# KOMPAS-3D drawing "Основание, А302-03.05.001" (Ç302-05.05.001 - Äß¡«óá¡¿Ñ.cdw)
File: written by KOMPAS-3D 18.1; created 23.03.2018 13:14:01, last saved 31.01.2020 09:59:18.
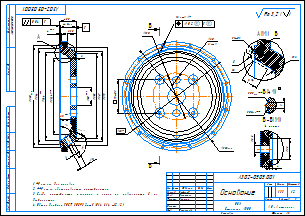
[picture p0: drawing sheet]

Sheet 1: A3, landscape

Document properties: Автор: Милов; Параметр неуказанной шероховатости: Ra 3,2; Полное имя файла: ..\3Д\А302-00.05.001 - Основание.m3d; Масса: 1.33492; Организация: Милов

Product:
- Part/product: Основание  | designation А302-03.05.001
    Материал: Полипропилен  ГОСТ 26996-86 (density 900 kg/m3)
    Масса: 1.33086
    Раздел спецификации: Детали
    Форматы листов документа: A3
- Part/product: Основание  | designation А302-00.05.001
    Материал: Полипропилен  ГОСТ 26996-86 (density 900 kg/m3)
    Масса: 1.33086
    Раздел спецификации: Детали
    Форматы листов документа: A3
    source file: \\192.168.87.28\Konstructor_doc\Мембранные насосы\Мембранный электропривод\А302-00.00.000 - ASTRA-302 (МЭ200)\Чертежи\А302-00.05.001 - Основание.cdw
- Part/product: Основание  | designation А302-04.05.001
    Материал: Полипропилен  ГОСТ 26996-86 (density 900 kg/m3)
    Масса: 1.33492
    Раздел спецификации: Детали
    Форматы листов документа: A3
    source file: ..\Чертежи ПВХ\А302-02.05.001 - Основание.cdw, ..\Чертежи Полипропилен\А302-03.05.001 - Основание.cdw
- Part/product: Основание  | designation А302-05.05.001
    Материал: Полипропилен  ГОСТ 26996-86 (density 900 kg/m3)
    Масса: 1.33492
    Раздел спецификации: Детали
    Форматы листов документа: A3

Title block, sheet 1: Наименование: Основание; designation: А302-05.05.001; Материал: ПВХ / Стержень  300; Масса: 1,33; scale: 1:2; Количество листов документа: 1; organisation: АО «Астерион»; Форматы листов документа: A3; stored path: \\192.168.87.28\Konstructor_doc\Мембранные насосы\Мембранный электропривод\А302-00.00.000 - ASTRA-302 (МЭ200)\Чертежи\А302-00.05.001 - Основание.cdw; Разработал: Лифлянд; Проверил: Борисенко; Т. контр.: Лучихин; Утвердил: Григорьева

Views: Вид 1, Местный разрез 1, Вид:3, Проекционный вид 2, Выносной элемент 3, Разрез 4, Выносной элемент 5, Выносной элемент А, Выносной элемент, Разрез В-В, Выносной элемент Б
Referenced files in D:\Мембранные насосы\Мембранный электропривод\А302-00.00.000 - ASTRA-302 (МЭ200)\3Д\: А302-00.05.001 - Основание.m3d
Referenced files in Z:\Мембранные насосы\Мембранный электропривод\А302-00.00.000 - ASTRA-302 (МЭ200)\3Д\: А302-00.05.001 - Основание.m3d
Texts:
  Ra 3,2
  Ra 3,2 ( )
Dimensions and other numbers on the sheet: 16; 9; 50; 4; 44,5; 272; 28; 280; 211,67; 244; 0,04; 23,5; 247; 235; 2; 264; 45,5; 302; 20; 2 отв.; 130; 287; 12 отв.; 7; 92±0,2; 6; 12; 2,5; 15; 1±0,1; 4 места; 8,5; 0,5; 1:2; 1,33

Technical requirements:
  *Размеры для справок.
  **Размер обеспечивается инструментом.
  Следы инструмента, царапины и риски на поверхности Д не
  допускаются.
  Общие допуски ГОСТ 30893.2-mK (H14, h14,  t2/2).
